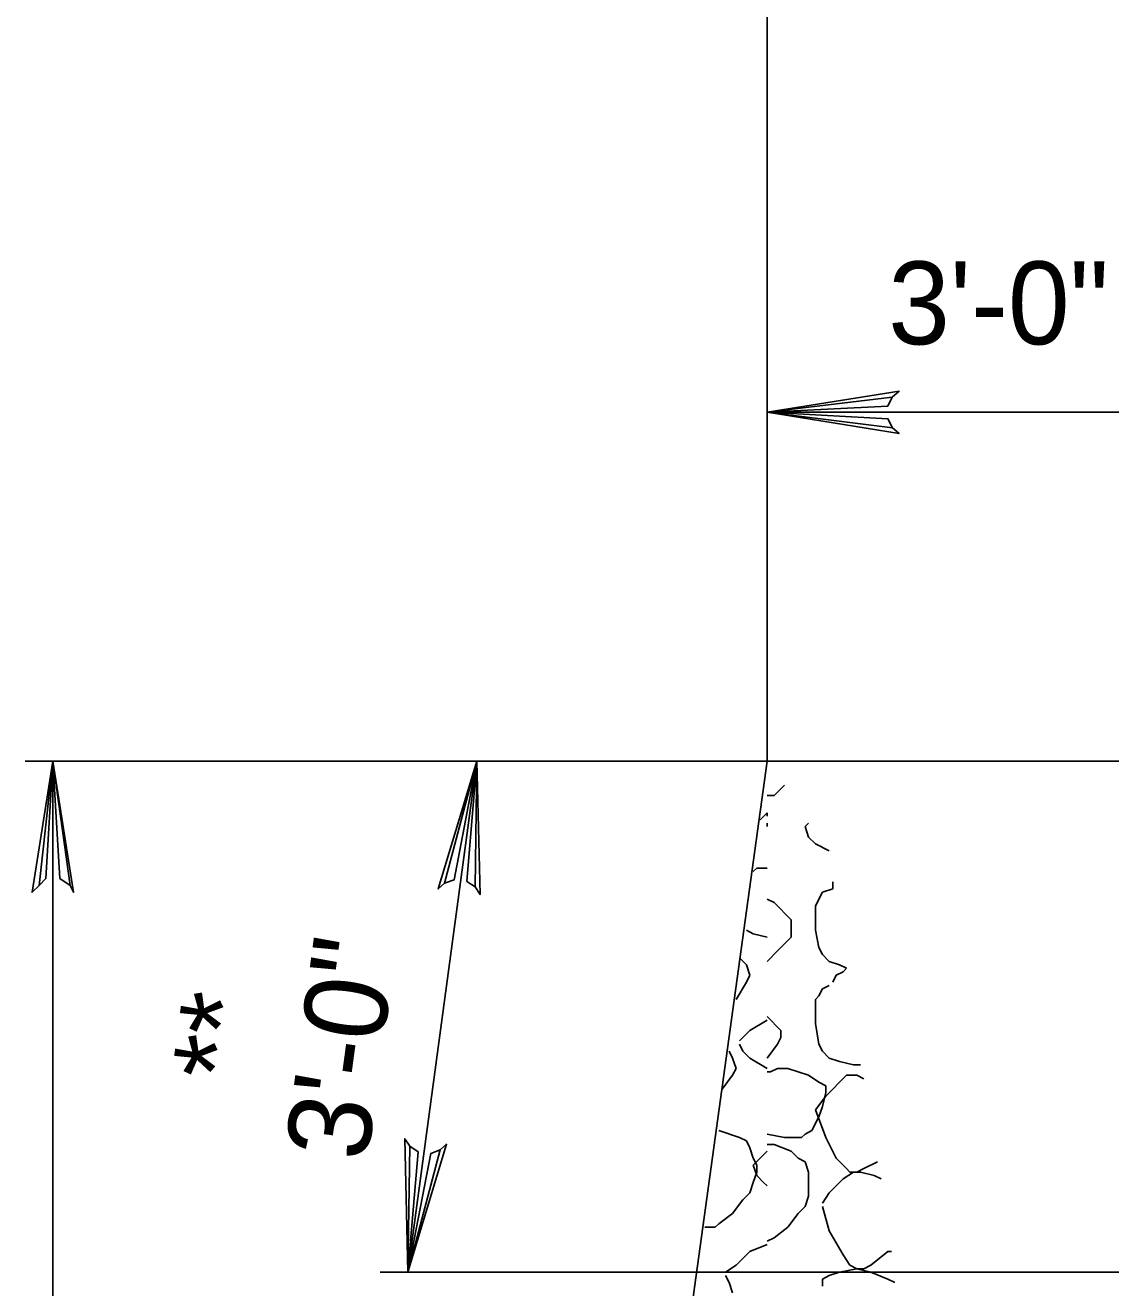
# Model space of a CAD drawing. Extents: x 593 to 1473, y 721 to 1315.
# Drawn here: x 888.93 to 928.22, y 1200.08 to 1245.77 of the extents above; entities that cross this region are included whole.
import ezdxf

# ---------------------------------------------------------------- set-up
doc = ezdxf.new("R2010")
doc.units = 0
doc.layers.add('1', color=7, linetype='Continuous')
doc.layers.add('2', color=7, linetype='Continuous')

msp = doc.modelspace()

# ---------------------------------------------------------------- linework, layer by layer
at = {"layer": '1'}
for points in [[(920.324, 1231.201), (920.155, 1231.53), (915.783, 1231.771), (920.324, 1231.201), (920.557, 1231.002), (915.783, 1231.771), (920.151, 1231.987), (920.311, 1232.312), (915.783, 1231.771), (920.557, 1232.53), (920.311, 1232.312)], [(904.11, 1214.723), (904.459, 1214.846), (905.283, 1219.146), (904.11, 1214.723), (903.882, 1214.519), (905.283, 1219.146), (904.912, 1214.789), (905.213, 1214.587), (905.283, 1219.146), (905.396, 1214.314), (905.213, 1214.587)], [(904.11, 1214.723), (904.459, 1214.846), (905.283, 1219.146), (904.11, 1214.723), (903.882, 1214.519), (905.283, 1219.146), (904.912, 1214.789), (905.213, 1214.587), (905.283, 1219.146), (905.396, 1214.314), (905.213, 1214.587)], [(903.956, 1205.07), (903.608, 1204.946), (902.783, 1200.646), (903.956, 1205.07), (904.185, 1205.274), (902.783, 1200.646), (903.154, 1205.004), (902.853, 1205.205), (902.783, 1200.646), (902.671, 1205.478), (902.853, 1205.205)]]:
    msp.add_lwpolyline(points, dxfattribs=at)
at = {"layer": '2'}
for p, q in [((915.783, 1219.146), (915.783, 1255.035)), ((915.783, 1220.646), (915.783, 1233.271)), ((934.408, 1231.771), (915.783, 1231.771)), ((914.908, 1219.146), (888.933, 1219.146)), ((889.933, 1144.896), (889.933, 1219.146)), ((943.658, 1219.146), (901.783, 1219.146)), ((902.783, 1200.646), (905.283, 1219.146)), ((905.533, 1144.896), (915.783, 1219.146)), ((914.908, 1200.646), (901.783, 1200.646)), ((902.783, 1200.646), (902.783, 1200.646)), ((952.908, 1200.646), (913.408, 1200.646))]:
    msp.add_line(p, q, dxfattribs=at)
for points in [[(889.433, 1214.646), (889.683, 1214.896), (889.933, 1219.146), (889.433, 1214.646), (889.183, 1214.396), (889.933, 1219.146), (890.183, 1214.896), (890.558, 1214.646), (889.933, 1219.146), (890.683, 1214.396), (890.558, 1214.646)], [(916.408, 1218.271), (916.033, 1217.896)], [(916.033, 1217.896), (915.783, 1217.896)], [(915.783, 1217.271), (915.533, 1217.021)], [(915.783, 1217.146), (915.783, 1217.271)], [(915.783, 1216.771), (915.783, 1216.896)], [(917.158, 1216.771), (917.283, 1216.896)], [(917.283, 1216.396), (917.158, 1216.771)], [(917.533, 1216.146), (917.283, 1216.396)], [(918.033, 1215.896), (917.533, 1216.146)], [(915.283, 1215.146), (915.408, 1215.271)], [(915.408, 1215.271), (915.658, 1215.271)], [(915.658, 1215.271), (915.783, 1215.271)], [(917.783, 1214.396), (918.158, 1214.521)], [(918.158, 1214.521), (918.158, 1214.771)], [(915.783, 1214.146), (916.033, 1214.021)], [(916.033, 1214.021), (916.658, 1213.396)], [(917.533, 1213.896), (917.658, 1214.146)], [(917.658, 1214.146), (917.783, 1214.396)], [(917.533, 1213.521), (917.533, 1213.896)], [(917.533, 1213.021), (917.533, 1213.521)], [(916.658, 1213.396), (916.658, 1213.146)], [(916.658, 1213.146), (916.658, 1212.771)], [(915.283, 1212.896), (915.033, 1213.021)], [(915.783, 1212.771), (915.283, 1212.896)], [(916.658, 1212.771), (916.158, 1212.271)], [(917.658, 1212.396), (917.533, 1213.021)], [(916.158, 1212.271), (915.783, 1211.896)], [(917.783, 1212.146), (917.658, 1212.396)], [(918.033, 1211.896), (917.783, 1212.146)], [(914.783, 1212.021), (915.033, 1211.771)], [(915.033, 1211.771), (915.158, 1211.396)], [(918.408, 1211.771), (918.033, 1211.896)], [(918.658, 1211.646), (918.408, 1211.771)], [(915.158, 1211.396), (915.033, 1211.146)], [(918.158, 1211.146), (918.283, 1211.396)], [(918.283, 1211.396), (918.533, 1211.521)], [(918.533, 1211.521), (918.658, 1211.646)], [(915.033, 1211.146), (914.658, 1210.521)], [(917.658, 1210.646), (917.783, 1210.896)], [(917.783, 1210.896), (918.033, 1211.021)], [(917.533, 1210.521), (917.658, 1210.646)], [(917.533, 1210.146), (917.533, 1210.521)], [(915.783, 1209.896), (916.283, 1209.396)], [(917.533, 1209.646), (917.533, 1210.146)], [(914.783, 1209.021), (915.158, 1209.396)], [(915.158, 1209.396), (915.783, 1209.771)], [(915.783, 1209.771), (915.783, 1209.771)], [(916.283, 1209.396), (916.283, 1209.146)], [(917.658, 1208.896), (917.533, 1209.646)], [(916.283, 1209.146), (916.158, 1208.896)], [(914.408, 1208.646), (914.533, 1208.396)], [(914.908, 1208.646), (914.783, 1208.896)], [(915.158, 1208.396), (914.908, 1208.646)], [(916.158, 1208.896), (915.783, 1208.396)], [(917.783, 1208.646), (917.658, 1208.896)], [(918.033, 1208.396), (917.783, 1208.646)], [(914.533, 1208.396), (914.658, 1208.021)], [(915.783, 1208.021), (915.158, 1208.396)], [(918.408, 1208.271), (918.033, 1208.396)], [(918.908, 1208.146), (918.408, 1208.271)], [(919.158, 1208.146), (918.908, 1208.146)], [(914.533, 1207.771), (914.158, 1207.271)], [(914.658, 1208.021), (914.533, 1207.771)], [(915.783, 1208.021), (915.783, 1208.021)], [(915.783, 1207.896), (915.908, 1207.896)], [(915.908, 1207.896), (916.158, 1208.021)], [(916.158, 1208.021), (916.533, 1208.021)], [(916.533, 1208.021), (916.908, 1207.896)], [(916.908, 1207.896), (917.283, 1207.771)], [(917.283, 1207.771), (917.658, 1207.521)], [(918.408, 1207.521), (918.658, 1207.771)], [(918.658, 1207.771), (918.783, 1207.771)], [(918.783, 1207.771), (919.033, 1207.771)], [(919.033, 1207.771), (919.283, 1207.646)], [(917.658, 1207.521), (917.908, 1207.396)], [(917.908, 1207.146), (917.783, 1206.646)], [(917.908, 1207.396), (917.908, 1207.146)], [(917.908, 1207.021), (918.158, 1207.271)], [(918.158, 1207.271), (918.408, 1207.521)], [(917.533, 1206.521), (917.908, 1207.021)], [(917.658, 1206.271), (917.408, 1205.771)], [(917.908, 1205.521), (917.533, 1206.521)], [(917.783, 1206.646), (917.658, 1206.271)], [(914.033, 1205.771), (914.033, 1205.771)], [(914.033, 1205.771), (914.783, 1205.521)], [(917.408, 1205.771), (917.158, 1205.646)], [(914.783, 1205.521), (915.033, 1205.396)], [(915.033, 1205.396), (915.158, 1205.146)], [(916.408, 1205.521), (915.783, 1205.646)], [(917.033, 1205.521), (916.408, 1205.521)], [(917.158, 1205.646), (917.033, 1205.521)], [(918.283, 1204.771), (917.908, 1205.521)], [(915.158, 1205.146), (915.283, 1204.771)], [(915.283, 1204.521), (915.658, 1204.896)], [(915.658, 1204.896), (915.783, 1205.021)], [(915.783, 1205.271), (916.033, 1205.271)], [(916.033, 1205.271), (916.658, 1205.021)], [(916.658, 1205.021), (916.908, 1204.771)], [(915.283, 1204.771), (915.408, 1204.521)], [(915.408, 1204.146), (915.283, 1204.521)], [(915.408, 1204.521), (915.408, 1204.271)], [(916.908, 1204.771), (917.158, 1204.646)], [(917.158, 1204.646), (917.283, 1204.271)], [(918.658, 1204.396), (918.283, 1204.771)], [(918.783, 1204.271), (918.658, 1204.396)], [(919.283, 1204.396), (919.033, 1204.271)], [(919.783, 1204.646), (919.283, 1204.396)], [(915.408, 1204.271), (915.283, 1203.896)], [(915.658, 1203.896), (915.408, 1204.146)], [(917.283, 1204.271), (917.283, 1204.021)], [(917.283, 1204.021), (917.283, 1203.771)], [(918.408, 1203.896), (918.533, 1204.021)], [(918.533, 1204.021), (918.908, 1204.271)], [(919.033, 1204.271), (918.783, 1204.271)], [(918.908, 1204.271), (919.033, 1204.271)], [(919.033, 1204.271), (919.158, 1204.271)], [(919.158, 1204.271), (919.658, 1204.146)], [(919.658, 1204.146), (919.908, 1204.021)], [(915.158, 1203.521), (914.908, 1203.271)], [(915.283, 1203.896), (915.158, 1203.521)], [(915.783, 1203.771), (915.658, 1203.896)], [(917.283, 1203.771), (917.283, 1203.396)], [(917.783, 1203.146), (918.033, 1203.521)], [(918.033, 1203.521), (918.408, 1203.896)], [(914.908, 1203.271), (914.533, 1202.771)], [(917.158, 1203.021), (916.908, 1202.771)], [(917.283, 1203.396), (917.158, 1203.021)], [(918.033, 1202.146), (917.783, 1203.021)], [(914.533, 1202.771), (914.033, 1202.396)], [(916.908, 1202.771), (916.533, 1202.271)], [(913.908, 1202.271), (913.533, 1202.271)], [(914.033, 1202.396), (913.908, 1202.271)], [(916.533, 1202.271), (916.033, 1201.896)], [(918.533, 1201.271), (918.033, 1202.146)], [(915.158, 1201.396), (915.783, 1201.646)], [(916.033, 1201.896), (915.783, 1201.771)], [(914.658, 1200.896), (915.158, 1201.396)], [(918.783, 1200.896), (918.533, 1201.271)], [(920.158, 1201.396), (919.533, 1200.896)], [(920.283, 1201.396), (920.158, 1201.396)], [(914.283, 1200.646), (914.658, 1200.896)], [(918.408, 1200.646), (919.033, 1200.771)], [(919.033, 1200.771), (918.783, 1200.896)], [(919.033, 1200.771), (919.533, 1200.646)], [(919.283, 1200.771), (919.033, 1200.771)], [(919.533, 1200.896), (919.283, 1200.771)], [(914.408, 1200.271), (914.283, 1200.521)], [(914.533, 1199.896), (914.408, 1200.271)], [(917.783, 1200.396), (918.033, 1200.521)], [(917.783, 1200.146), (917.783, 1200.396)], [(918.033, 1200.521), (918.408, 1200.646)], [(919.533, 1200.646), (920.158, 1200.396)], [(920.158, 1200.396), (920.408, 1200.271)], [(920.408, 1200.271), (920.408, 1200.271)]]:
    msp.add_lwpolyline(points, dxfattribs=at)

# ---------------------------------------------------------------- texts
msp.add_text('3\'-0"', height=3, dxfattribs=at).set_placement((920.168, 1234.225))
for s, p in [('3\'-0"', (901.307, 1204.609)), ('**', (897.209, 1207.428))]:
    msp.add_text(s, height=3, rotation=82.316, dxfattribs=at).set_placement(p)

doc.saveas('drawing.dxf')
